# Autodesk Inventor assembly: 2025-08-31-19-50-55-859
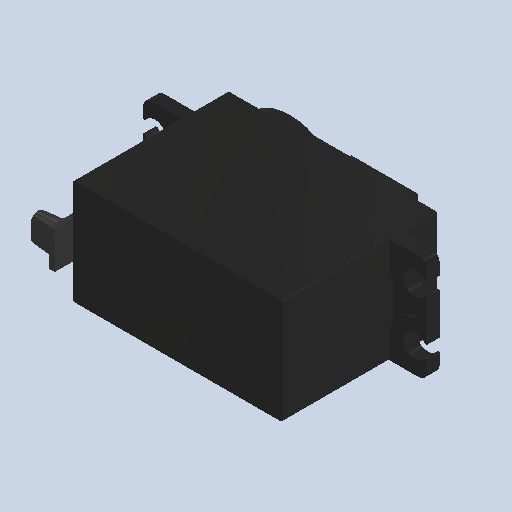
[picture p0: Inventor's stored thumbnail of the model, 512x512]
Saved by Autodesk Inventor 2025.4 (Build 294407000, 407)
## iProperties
Created: 2026-09
Part Number: 2025-08-31-19-50-55-859
Document SubType Name: Assembly
Designer: AdminForWorker
Title: com_top
Author: AdminForWorker
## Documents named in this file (3)
- c:\worker\convert-fusion-r05-cosv3\tmp\job-1\19\temp\files\ca3d996b-dda0-445d-8bee-12a194174ca8\com_top_2.iam
- c:\worker\convert-fusion-r05-cosv3\tmp\job-1\19\temp\files\ca3d996b-dda0-445d-8bee-12a194174ca8\Component8.ipt
- c:\worker\convert-fusion-r05-cosv3\tmp\job-1\19\temp\files\ca3d996b-dda0-445d-8bee-12a194174ca8\Part16.ipt
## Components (2 placed, 2 different names)
1. Component8:1
2. Part16
